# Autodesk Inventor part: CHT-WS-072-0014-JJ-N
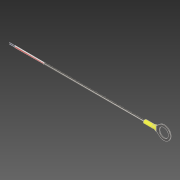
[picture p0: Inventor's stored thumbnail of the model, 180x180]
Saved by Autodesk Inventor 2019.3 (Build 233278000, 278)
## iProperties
Created: 2017-05
Part Number: CHT-WS-072-0014-JJ-N
Material: Generic
Document SubType Name: Modeling
Designer: JN
Density: 1 g/cm^3
Appearance: Steel - Polished
Author: JN
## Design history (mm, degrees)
sketch "Sketch1"
  geometry: L1 (-5.054, 7.651)-(-10.033, 3.471); L2 (-10.033, 3.471)-(-10.033, -3.536); L3 (-10.033, -3.536)-(-5.054, -7.716); L4 (-10.033, -0.032)-(11.43, -0.032); L5 (5.836, 8.965)-(5.836, -9.03); C1 r 6.985 at (1.397, -0.032); A1 r 10.033 centre (1.397, -0.032) between (-5.054, -7.716) and (-5.054, 7.651)
  constraints: 10 end point, 5 point on circle, 2 centre point, 2 tangent, 2 vertical, 1 coincident, 1 midpoint, 1 other
  dimensions: "d0" = 13.97 diameter of C1; "d1" = 20.066 diameter of A1; "d66" = 4.445 distance edge to line of C1 L2
extrude "Extrusion1" new body sketch "Sketch1" stored distance "d7" = 1.0668; taper "d8" = 0 deg
sketch "Sketch3"
  geometry: L1 (0, 0)-(-1.067, 0) reference; L2 (0, 7.007)-(0, 0) reference; L3 (0, 7.007)-(-1.067, 7.007) reference; L4 (-1.067, 0)-(-1.067, 7.007) reference; L5 (0.317, 7.324)-(-1.702, 7.324); L6 (-1.702, 7.324)-(-1.702, -0.318); L7 (-1.702, -0.318)-(0.317, -0.318); L8 (0.317, -0.318)-(0.317, 7.324); L9 (-0.692, 7.324)-(-0.692, -0.318); L10 (0.317, 3.503)-(-1.702, 3.503); 1 further point
  constraints: 12 end point, 6 parallel, 5 midpoint, 1 horizontal, 1 perpendicular
  dimensions: "d15" = 0.3175 distance between parallel lines of L2 L8; "d16" = 0.635 distance between parallel lines of L4 L6; "d17" = 0.3175 distance between parallel lines of L3 L5; "d18" = 0.3175 distance between parallel lines of L1 L7
  node "Projected Loop1"
workplane "Work Plane1"
sketch "Sketch4"
  geometry: L1 (0.317, -0.318)-(0.317, 7.324) reference; L2 (0.317, 7.324)-(-1.702, 7.324) reference; L3 (-1.702, 7.324)-(-1.702, -0.318) reference; L4 (-1.702, -0.318)-(0.317, -0.318) reference; L5 (0.317, 3.503)-(-1.702, 3.503); L6 (-0.692, 7.324)-(-0.692, -0.318); L7 (-2.337, 5.439)-(-2.337, 1.568); A1 r 2.54 centre (-0.692, 3.503) between (-2.337, 1.568) and (-2.337, 5.439); 2 further points
  constraints: 6 end point, 5 midpoint, 2 point on circle, 1 centre point, 1 coincident, 1 point on line, 1 vertical
  dimensions: "d37" = 5.08 diameter of A1; "d38" = 0.635 distance between parallel lines of L3 L7
sketch "3D Sketch1"
loft "Loft1" sketch "Sketch4", "3D Sketch1" dims "d21" = 0, "d22" = 90 deg, "d25" = 0, "d26" = 90 deg, "d39" = 0, "d40" = 90 deg
sketch "Sketch5"
  geometry: L1 (-1.645, 1.936)-(-1.645, -1.936) reference; A1 r 2.54 centre (0, 0) between (0.07, -2.539) and (0.857, 2.391) reference; A2 r 2.54 centre (0, 0) between (0.857, 2.391) and (-1.645, 1.936) reference; A3 r 2.54 centre (0, 0) between (0.857, 2.391) and (-1.645, 1.936) reference; A4 r 2.54 centre (0, 0) between (-1.645, -1.936) and (0.07, -2.539) reference; A5 r 2.54 centre (0, 0) between (0.07, -2.539) and (0.857, 2.391) reference
extrude "Extrusion3" new body sketch "Sketch5" distance "d27" = 12.7; taper "d28" = 0 deg
sketch "Sketch6" dims "d29" = 1.27, "d30" = 1.778
  geometry: L1 (0, 3.446)-(2.019, 3.446); L2 (2.54, 0)-(-1.645, 0); L3 (-1.645, 1.936)-(-1.645, -1.936) reference; A1 r 2.54 centre (0, 0) between (0.07, -2.539) and (0.857, 2.391) reference; 2 further points; 1 other entity
  constraints: 4 end point, 2 midpoint, 1 point on circle, 2 other
extrude "Extrusion4" cut sketch "Sketch6" stored distance "d32" = 12.7; taper "d33" = 0 deg
extrude "Extrusion5" new body sketch "Sketch6" distance "d34" = 152.4; taper "d35" = 0 deg
workplane "Work Plane2"
sketch "Sketch8"
  geometry: C1 r 0.635 at (0.187, 0.635) reference; C2 r 0.635 at (0.187, -0.635) reference; C3 r 0.635 at (0.187, 0.952); C4 r 0.635 at (0.187, -0.953)
  constraints: 2 centre point
  dimensions: "d43" = 1.27 diameter of C3; "d45" = 0.3175 distance of C1.centre C3.centre; "d46" = 1.27 diameter of C4; "d47" = 0.3175 distance of C2.centre C4.centre
sketch "3D Sketch2"
loft "Loft2" dims "d48" = 0, "d49" = 90 deg, "d50" = 0, "d51" = 90 deg, "d52" = 0, "d53" = 90 deg
loft "Loft3" dims "d54" = 0, "d55" = 90 deg, "d56" = 0, "d57" = 90 deg, "d58" = 0, "d59" = 90 deg
sketch "Sketch9"
  geometry: C1 r 0.381 at (0, 0)
  constraints: 1 centre point
  dimensions: "d60" = 0.762 diameter of C1
sketch "Sketch10"
  geometry: C1 r 0.381 at (0, 0)
  constraints: 1 centre point
  dimensions: "d61" = 0.762 diameter of C1
extrude "Extrusion6" join sketch "Sketch9" distance "d62" = 8.46667; taper "d63" = 0 deg
extrude "Extrusion7" join sketch "Sketch10" distance "d64" = 8.46667; taper "d65" = 0 deg
body "Solid1"
sketch "Sketch7"
  geometry: L1 (1.01, 1.395)-(1.01, -1.395) reference; L2 (-1.048, 0)-(1.492, 0); C1 r 0.635 at (0.187, 0.635); C2 r 0.635 at (0.187, -0.635); 3 further points; 3 other entities
  constraints: 4 end point, 2 centre point, 2 tangent, 2 vertical, 1 horizontal, 8 other
  dimensions: "d41" = 1.27 diameter of C1
body "Solid2"
body "Solid3"
body "Solid4"
node "Projected Loop5"
other parameters: "d3" = 14.986 (derived), "d5" = 10.49782 (derived), "d19" = 5.08, "d42" = 44.45
